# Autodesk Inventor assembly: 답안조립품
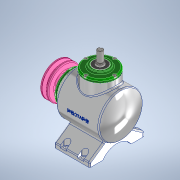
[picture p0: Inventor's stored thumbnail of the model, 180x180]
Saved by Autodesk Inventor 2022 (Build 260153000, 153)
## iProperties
Created: 2023-04
Part Number: 답안조립품
Document SubType Name: Assembly
Designer: Admin
Author: Admin
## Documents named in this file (17)
- C:\Users\Admin\Desktop\730411V1003\답안조립품.iam
- C:\Users\Admin\Desktop\730411V1003\본체.ipt
- C:\Users\Admin\Desktop\730411V1003\부품\커버.ipt
- C:\Users\Admin\Desktop\730411V1003\부품\베어링 6203.ipt
- C:\Users\Admin\Desktop\730411V1003\부품\오일실 17 x 32 x 8.ipt
- C:\Users\Admin\Desktop\730411V1003\부품\메인 축.ipt
- 메인 축.ipt
- C:\Users\Admin\Desktop\730411V1003\부품\키 5 x 5 x 14.ipt
- C:\Users\Admin\Desktop\730411V1003\부품\메인 베벨기어.ipt
- C:\Users\Admin\Desktop\730411V1003\부품\서브 축.ipt
- 서브 축.ipt
- C:\Users\Admin\Desktop\730411V1003\부품\키 4 x 4 x 14.ipt
- C:\Users\Admin\Desktop\730411V1003\부품\서브 베벨기어.ipt
- C:\Users\Admin\Desktop\730411V1003\부품\V-벨트풀리.ipt
- C:\Users\Admin\Desktop\730411V1003\부품\볼트 M4 x 10.ipt
- C:\Users\Admin\Desktop\730411V1003\부품\육각볼트 M4 x 8.ipt
- C:\Users\Admin\Desktop\730411V1003\부품\와셔 4 x 16.ipt
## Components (1 placed, 1 different names)
1. V-벨트풀리:1
